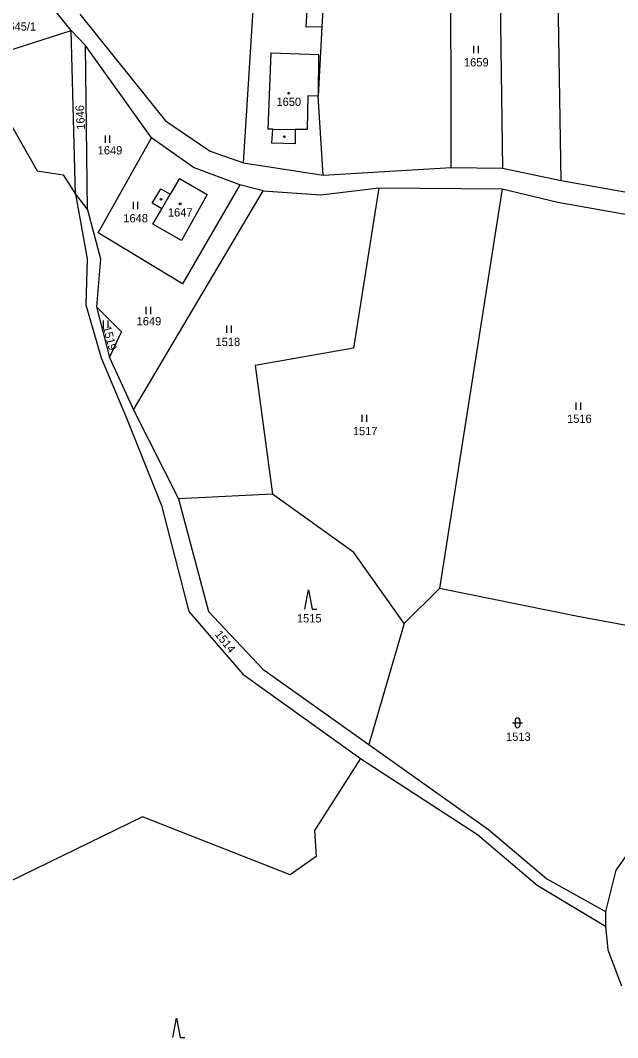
# Model space of a CAD drawing. Extents: x -670359 to -668019, y -978807 to -976674.
# Drawn here: x -669263 to -669140.5, y -978515.9 to -978307.2 of the extents above; entities that cross this region are included whole.
import ezdxf

# ---------------------------------------------------------------- set-up
doc = ezdxf.new("R2010")
doc.units = 0
for name, color, linetype in [('Hranice parcel', 7, 'Continuous'), ('Parcelní čísla', 7, 'Continuous'), ('Vnitřní kresba', 7, 'Continuous'), ('Značky budov', 7, 'Continuous'), ('Značky kultur', 7, 'Continuous')]:
    doc.layers.add(name, color=color, linetype=linetype)

msp = doc.modelspace()

# ---------------------------------------------------------------- linework, layer by layer
at = {"layer": 'Hranice parcel'}
for points in [[(-669174.69, -978337.35), (-669174.73, -978288.64)], [(-669164.78, -978293.31), (-669164.12, -978337.46)], [(-669152.14, -978339.99), (-669152.85, -978293.75)], [(-669252.6, -978309.23), (-669261.68, -978298.02)], [(-669217.26, -978336.41), (-669215.04, -978300.68)], [(-669204.4, -978308.56), (-669204.1, -978302.64)], [(-669200.9, -978302.67), (-669201.2, -978308.51)], [(-669250.88, -978305.89), (-669233.26, -978327.76)], [(-669201.2, -978308.51), (-669204.4, -978308.56)], [(-669201.2, -978308.51), (-669201.99, -978322.74)], [(-669283.33, -978319.11), (-669252.6, -978309.23)], [(-669249.67, -978312.31), (-669252.6, -978309.23)], [(-669251.75, -978342.84), (-669252.6, -978309.23)], [(-669236.18, -978331.25), (-669249.67, -978312.31)], [(-669249.3, -978346.06), (-669249.67, -978312.31)], [(-669212.23, -978329.51), (-669211.58, -978313.84)], [(-669211.58, -978313.84), (-669201.9, -978314.18)], [(-669201.9, -978314.18), (-669201.99, -978322.74)], [(-669204.07, -978322.64), (-669204.22, -978329.59)], [(-669201.99, -978322.74), (-669204.07, -978322.64)], [(-669200.96, -978338.91), (-669201.99, -978322.74)], [(-669233.26, -978327.76), (-669224.12, -978334.02)], [(-669264.97, -978328.54), (-669259.62, -978338.03)], [(-669211.27, -978329.52), (-669212.23, -978329.51)], [(-669211.46, -978332.39), (-669211.27, -978329.52)], [(-669204.22, -978329.59), (-669206.7, -978329.57)], [(-669206.7, -978329.57), (-669206.65, -978332.53)], [(-669247.11, -978350.73), (-669236.18, -978331.25)], [(-669227.52, -978337.34), (-669236.18, -978331.25)], [(-669224.12, -978334.02), (-669217.26, -978336.41)], [(-669206.65, -978332.53), (-669211.46, -978332.39)], [(-669259.62, -978338.03), (-669254.27, -978338.89)], [(-669218.03, -978340.88), (-669227.52, -978337.34)], [(-669217.26, -978336.41), (-669200.96, -978338.91)], [(-669200.96, -978338.91), (-669174.69, -978337.35)], [(-669174.69, -978337.35), (-669164.12, -978337.46)], [(-669164.12, -978337.46), (-669152.14, -978339.99)], [(-669254.27, -978338.89), (-669251.75, -978342.84)], [(-669230.42, -978339.59), (-669232.31, -978342.85)], [(-669230.42, -978339.59), (-669224.73, -978342.89)], [(-669152.14, -978339.99), (-669125.22, -978344.84)], [(-669239.81, -978387.04), (-669213.24, -978342.13)], [(-669235.98, -978344.68), (-669234.26, -978341.72)], [(-669234.26, -978341.72), (-669232.31, -978342.85)], [(-669218.03, -978340.88), (-669229.77, -978361.23)], [(-669213.24, -978342.13), (-669218.03, -978340.88)], [(-669213.24, -978342.13), (-669201.4, -978342.98)], [(-669201.4, -978342.98), (-669189.54, -978341.51)], [(-669189.54, -978341.51), (-669194.69, -978374.41)], [(-669189.54, -978341.51), (-669164.25, -978341.7)], [(-669164.25, -978341.7), (-669177.04, -978423.71)], [(-669164.25, -978341.7), (-669152.83, -978344.47)], [(-669251.75, -978342.84), (-669249.33, -978356.06)], [(-669251.75, -978342.84), (-669249.3, -978346.06)], [(-669224.73, -978342.89), (-669230, -978352.31)], [(-669152.83, -978344.47), (-669124.7, -978349.49)], [(-669249.3, -978346.06), (-669246.61, -978356.09)], [(-669234.03, -978345.81), (-669235.98, -978344.68)], [(-669235.89, -978349.01), (-669234.03, -978345.81)], [(-669229.77, -978361.23), (-669247.11, -978350.73)], [(-669230, -978352.31), (-669235.89, -978349.01)], [(-669249.33, -978356.06), (-669249.6, -978365.5)], [(-669246.61, -978356.09), (-669247.43, -978365.92)], [(-669249.6, -978365.5), (-669246.5, -978376.41)], [(-669247.43, -978365.92), (-669244.74, -978376.35)], [(-669242.28, -978371.09), (-669247.43, -978365.92)], [(-669244.74, -978376.35), (-669242.28, -978371.09)], [(-669194.69, -978374.41), (-669214.9, -978377.95)], [(-669246.5, -978376.41), (-669241.19, -978388.94)], [(-669244.74, -978376.35), (-669239.81, -978387.04)], [(-669214.9, -978377.95), (-669211.34, -978404.38)], [(-669239.81, -978387.04), (-669230.64, -978405.29)], [(-669241.19, -978388.94), (-669234.09, -978406.7)], [(-669211.34, -978404.38), (-669230.64, -978405.29)], [(-669194.65, -978416.32), (-669211.34, -978404.38)], [(-669234.09, -978406.7), (-669228.48, -978428.43)], [(-669230.64, -978405.29), (-669224.48, -978428.47)], [(-669184.32, -978430.91), (-669194.65, -978416.32)], [(-669177.04, -978423.71), (-669184.32, -978430.91)], [(-669148.68, -978429.45), (-669177.04, -978423.71)], [(-669228.48, -978428.43), (-669217.41, -978441.27)], [(-669224.48, -978428.47), (-669213.32, -978440.27)], [(-669126.15, -978433.62), (-669148.68, -978429.45)], [(-669184.32, -978430.91), (-669191.55, -978455.71)], [(-669213.32, -978440.27), (-669191.55, -978455.71)], [(-669217.41, -978441.27), (-669193.26, -978458.57)], [(-669191.55, -978455.71), (-669166.99, -978473.17)], [(-669193.26, -978458.57), (-669202.73, -978473.33)], [(-669193.26, -978458.57), (-669169.25, -978474.18)], [(-669126.32, -978460.97), (-669140.91, -978481.53)], [(-669237.99, -978470.53), (-669290.38, -978496.06)], [(-669207.68, -978482.43), (-669237.99, -978470.53)], [(-669202.73, -978473.33), (-669202.35, -978478.73)], [(-669166.99, -978473.17), (-669155.09, -978483.29)], [(-669169.25, -978474.18), (-669157.03, -978484.55)], [(-669202.35, -978478.73), (-669207.68, -978482.43)], [(-669140.91, -978481.53), (-669143, -978489.98)], [(-669155.09, -978483.29), (-669143, -978489.98)], [(-669157.03, -978484.55), (-669143.03, -978493.02)], [(-669143, -978489.98), (-669143.03, -978493.02)], [(-669143.03, -978493.02), (-669142.52, -978497.83)], [(-669142.52, -978497.83), (-669139.72, -978505.22)]]:
    msp.add_lwpolyline(points, dxfattribs=at)
at = {"layer": 'Vnitřní kresba'}
for points in [[(-669211.27, -978329.52), (-669206.7, -978329.57)], [(-669234.03, -978345.81), (-669232.31, -978342.85)]]:
    msp.add_lwpolyline(points, dxfattribs=at)
at = {"layer": 'Značky budov'}
for centre in [(-669208.02, -978322.12), (-669230.27, -978344.81)]:
    msp.add_circle(centre, 0.175, dxfattribs=at)
at = {"layer": 'Značky kultur'}
for p, q in [((-669170.09, -978312.42), (-669170.09, -978313.92)), ((-669169.09, -978313.92), (-669169.09, -978312.42)), ((-669245.67, -978330.76), (-669245.67, -978332.26)), ((-669244.67, -978332.26), (-669244.67, -978330.76)), ((-669239.93, -978344.41), (-669239.93, -978345.91)), ((-669238.93, -978345.91), (-669238.93, -978344.41)), ((-669237.28, -978365.94), (-669237.28, -978367.44)), ((-669236.28, -978367.44), (-669236.28, -978365.94)), ((-669246.05, -978368.71), (-669246.05, -978370.21)), ((-669245.05, -978370.21), (-669245.05, -978368.71)), ((-669220.75, -978369.77), (-669220.75, -978371.27)), ((-669219.75, -978371.27), (-669219.75, -978369.77)), ((-669149.09, -978385.54), (-669149.09, -978387.04)), ((-669148.09, -978387.04), (-669148.09, -978385.54)), ((-669192.99, -978388.06), (-669192.99, -978389.56)), ((-669191.99, -978389.56), (-669191.99, -978388.06)), ((-669161.57, -978450.77), (-669161.57, -978451.77)), ((-669160.57, -978450.77), (-669160.57, -978451.77)), ((-669162.07, -978451.27), (-669160.07, -978451.27))]:
    msp.add_line(p, q, dxfattribs=at)
for points in [[(-669204.71, -978427.98), (-669203.96, -978423.98), (-669203.21, -978427.98), (-669202.21, -978427.98)], [(-669231.8, -978515.86), (-669231.05, -978511.86), (-669230.3, -978515.86), (-669229.3, -978515.86)]]:
    msp.add_lwpolyline(points, dxfattribs=at)
for centre in [(-669208.02, -978322.12), (-669208.89, -978331.04), (-669234.2, -978343.87), (-669230.27, -978344.81)]:
    msp.add_circle(centre, 0.175, dxfattribs=at)
for centre, start, end in [((-669161.07, -978450.77), 0, 180), ((-669161.07, -978451.77), 180, 0)]:
    msp.add_arc(centre, 0.5, start, end, dxfattribs=at)

# ---------------------------------------------------------------- texts
at = {"layer": 'Parcelní čísla'}
for s, p in [('1645/1', (-669266.77, -978309.27)), ('1659', (-669172.05, -978316.62)), ('1650', (-669210.52, -978324.72)), ('1649', (-669247.18, -978334.68)), ('1647', (-669232.77, -978347.41)), ('1648', (-669241.93, -978348.61)), ('1649', (-669239.2, -978369.74)), ('1518', (-669223.01, -978373.98)), ('1516', (-669150.91, -978389.74)), ('1517', (-669194.85, -978392.26)), ('1515', (-669206.32, -978430.68)), ('1513', (-669163.43, -978454.97))]:
    msp.add_text(s, height=1.7, dxfattribs=at).set_placement(p)
for s, rotation, p in [('1646', 93.3619, (-669249.77, -978329.55)), ('1519', 284.9294, (-669246.15, -978370.12)), ('1514', 308.4997, (-669223.26, -978433.16))]:
    msp.add_text(s, height=1.7, rotation=rotation, dxfattribs=at).set_placement(p)

doc.saveas('drawing.dxf')
